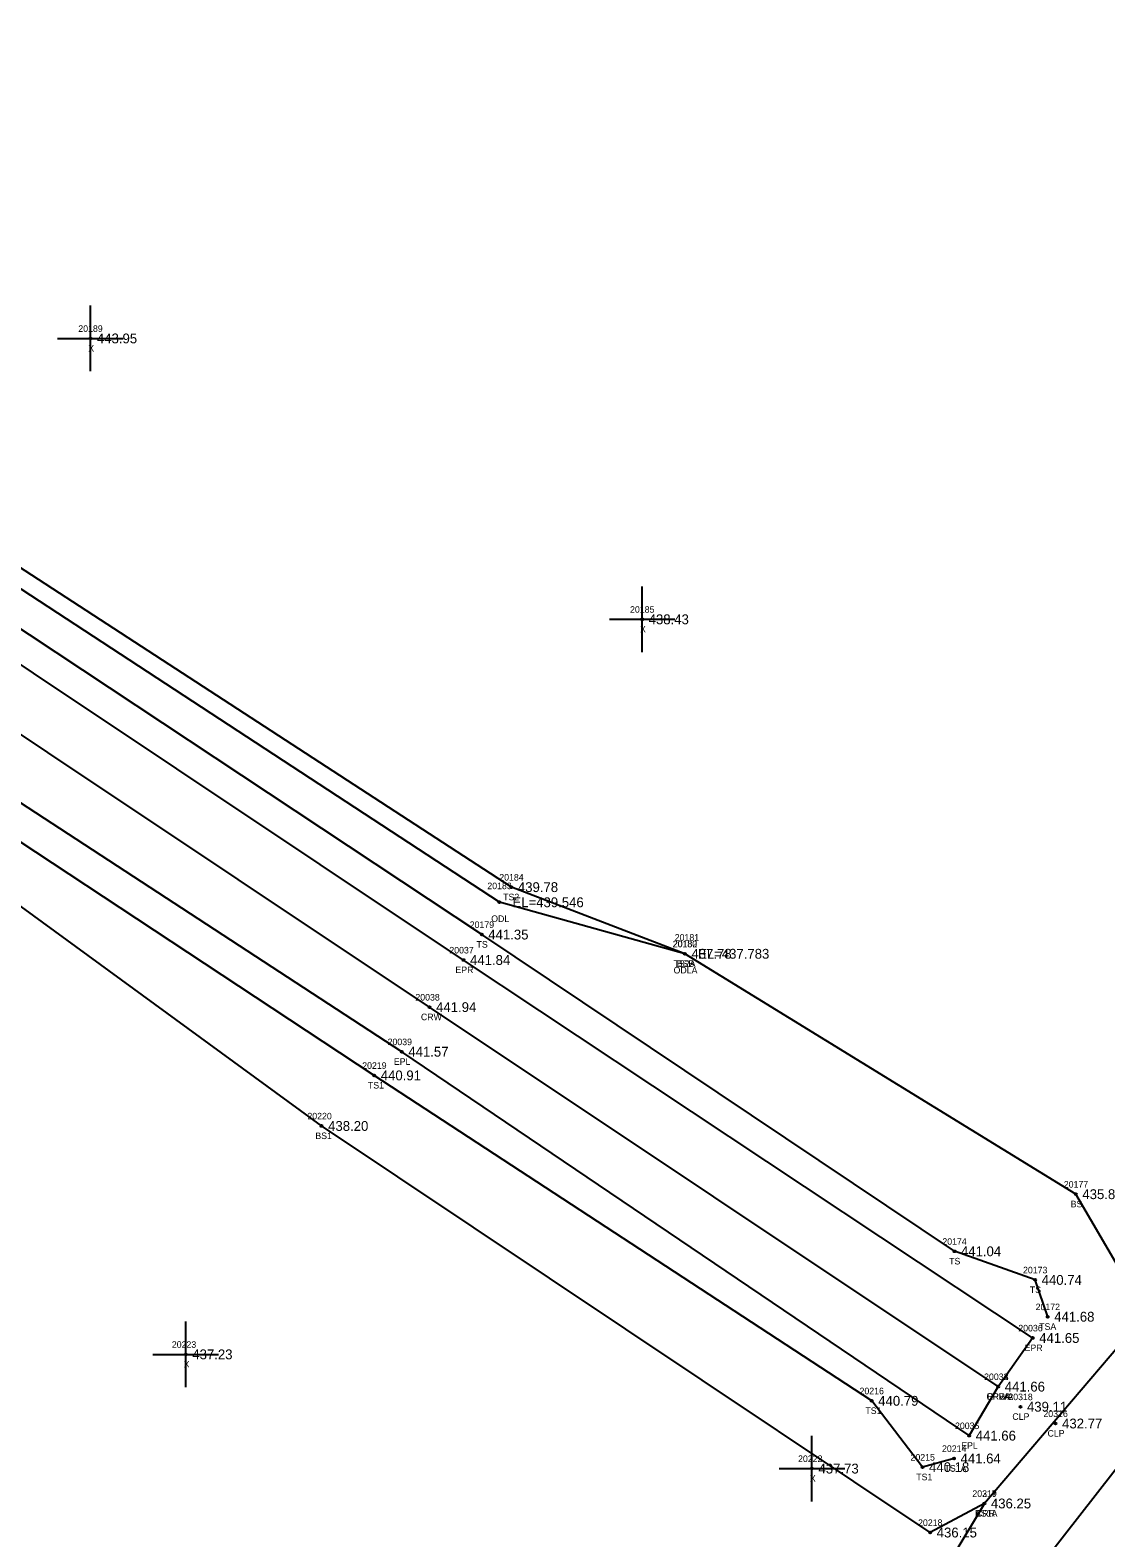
# Model space of a CAD drawing. Extents: x 1797709 to 1799052, y 896018 to 896955.
# Drawn here: x 1798214.6 to 1798378.7, y 896474.6 to 896704.4 of the extents above; entities that cross this region are included whole.
import ezdxf

# ---------------------------------------------------------------- set-up
doc = ezdxf.new("R2010")
doc.units = 0
for name, color, linetype in [('RD_DTM_BkLn1', 7, 'Continuous'), ('RD_DTM_BkLn2', 7, 'Continuous'), ('RD_DTM_BkLn_txCode', 7, 'Continuous'), ('RD_EX_H2O', 7, 'Continuous'), ('RD_EX_H2O_txCode', 7, 'Continuous'), ('RD_EX_Misc', 7, 'Continuous'), ('RD_EX_Misc_txCode', 7, 'Continuous'), ('RD_EX_Road', 7, 'Continuous'), ('RD_EX_Road_txCode', 7, 'Continuous'), ('RD_EX_TX_H2O_ELEV', 7, 'Continuous'), ('RD_EX_TX_Misc_ELEV', 7, 'Continuous'), ('RD_EX_TX_Road_ELEV', 7, 'Continuous'), ('RD_HC_Survey_ELEV', 7, 'Continuous'), ('RD_HC_Survey_txCode', 7, 'Continuous'), ('RD_SMD_Locator', 7, 'Continuous')]:
    doc.layers.add(name, color=color, linetype=linetype)

msp = doc.modelspace()

# ---------------------------------------------------------------- linework, layer by layer
at = {"layer": 'RD_DTM_BkLn1'}
msp.add_lwpolyline([(1798362.28, 896497.65), (1798275.53, 896555.51), (1798188.06, 896613.78), (1798100.6, 896671.09), (1798012.14, 896729.83), (1797925.7, 896787.19), (1797839.16, 896844.44), (1797754.21, 896899.34)], dxfattribs=at)
at = {"layer": 'RD_DTM_BkLn2'}
for points in [[(1798369.83, 896508.31), (1798367.91, 896513.92), (1798355.6, 896518.28), (1798283.49, 896566.57), (1798194.13, 896625.72), (1798108.66, 896683.13), (1798020.94, 896741.77), (1797934.88, 896798.69), (1797845.83, 896857.42), (1797757.7, 896918.3)], [(1798314.49, 896563.64), (1798288.01, 896573.8), (1798198.07, 896632.21), (1798113.28, 896689.71), (1798026.02, 896748.38), (1797939.51, 896805.48), (1797849.3, 896863.45), (1797757.7, 896918.3)], [(1798355.54, 896486.7), (1798350.74, 896485.38), (1798342.98, 896495.49), (1798267.09, 896545.1), (1798179.21, 896602.99), (1798092.54, 896661.13), (1798003.24, 896719.48), (1797918.21, 896775.43), (1797832.05, 896831.86), (1797744.82, 896887.66)], [(1798360.17, 896479.84), (1798351.9, 896475.41), (1798259.06, 896537.39), (1798197.99, 896581.94)], [(1798380.86, 896504.02), (1798383.64, 896510.73), (1798374.12, 896526.99), (1798314.49, 896563.64)]]:
    msp.add_lwpolyline(points, dxfattribs=at)
at = {"layer": 'RD_EX_H2O'}
for points in [[(1798314.49, 896563.64), (1798286.18, 896571.49), (1798196.7, 896629.98), (1798111.06, 896686.41), (1798023.38, 896745.41), (1797937.01, 896802.03), (1797847.56, 896860.46), (1797757.7, 896918.3)], [(1798652.43, 896917.58), (1798601.94, 896827.15), (1798558.78, 896718.92), (1798516.66, 896628.32), (1798463.08, 896540.21), (1798439.21, 896521.86), (1798389.85, 896497.35), (1798369.72, 896471.55), (1798343.52, 896433.35), (1798291.39, 896374.31), (1798235.39, 896326.89), (1798184.99, 896269.63), (1798095.18, 896198.01), (1798023.89, 896139.85)], [(1798502.61, 896635.66), (1798452.16, 896551.79), (1798380.86, 896504.02), (1798360.17, 896479.84), (1798335.44, 896438.68), (1798277.37, 896387.2), (1798228.36, 896339.61), (1798175.66, 896278.7), (1798083.83, 896204.11), (1798020.11, 896146.19)]]:
    msp.add_lwpolyline(points, dxfattribs=at)
at = {"layer": 'RD_EX_Misc'}
for p, q in [((1798223.79, 896652.45), (1798223.79, 896662.45)), ((1798218.79, 896657.45), (1798228.79, 896657.45)), ((1798307.96, 896609.63), (1798307.96, 896619.63)), ((1798302.96, 896614.63), (1798312.96, 896614.63)), ((1798238.34, 896497.57), (1798238.34, 896507.57)), ((1798233.34, 896502.57), (1798243.34, 896502.57)), ((1798333.87, 896480.16), (1798333.87, 896490.16)), ((1798328.87, 896485.16), (1798338.87, 896485.16))]:
    msp.add_line(p, q, dxfattribs=at)
at = {"layer": 'RD_EX_Road'}
for points in [[(1798362.28, 896497.65), (1798367.54, 896505.07), (1798280.71, 896562.69), (1798193.2, 896621.02), (1798104.98, 896679.23), (1798017.88, 896737.39), (1797930.72, 896795.63), (1797844.07, 896853.07), (1797758.11, 896906.97)], [(1798362.28, 896497.65), (1798357.85, 896490.18), (1798271.29, 896548.71), (1798183.2, 896606.17), (1798096.06, 896663.44), (1798006.57, 896721.75), (1797920.8, 896779.27), (1797834.41, 896836.87), (1797748.77, 896891.01)]]:
    msp.add_lwpolyline(points, dxfattribs=at)
at = {"layer": 'RD_SMD_Locator'}
for centre in [(1798223.79, 896657.45), (1798307.96, 896614.63), (1798288.01, 896573.8), (1798286.18, 896571.49), (1798283.49, 896566.57), (1798314.49, 896563.64), (1798314.49, 896563.64), (1798314.49, 896563.64), (1798280.71, 896562.69), (1798275.53, 896555.51), (1798271.29, 896548.71), (1798267.09, 896545.1), (1798259.06, 896537.39), (1798374.12, 896526.99), (1798355.6, 896518.28), (1798367.91, 896513.92), (1798369.83, 896508.31), (1798367.54, 896505.07), (1798238.34, 896502.57), (1798362.28, 896497.65), (1798362.28, 896497.65), (1798362.28, 896497.65), (1798342.98, 896495.49), (1798365.67, 896494.59), (1798357.85, 896490.18), (1798371.03, 896492.03), (1798350.74, 896485.38), (1798355.54, 896486.7), (1798333.87, 896485.16), (1798360.17, 896479.84), (1798360.17, 896479.84), (1798351.9, 896475.41)]:
    msp.add_circle(centre, 0.15, dxfattribs=at)

# ---------------------------------------------------------------- texts
at = {"layer": 'RD_DTM_BkLn_txCode'}
for s, p in [('20184', (1798286.17, 896574.8)), ('TS2', (1798286.76, 896571.8)), ('20179', (1798281.66, 896567.57)), ('TS', (1798282.7, 896564.57)), ('20180', (1798312.62, 896564.64)), ('20182', (1798312.66, 896564.64)), ('TS2A', (1798312.76, 896561.64)), ('BSB', (1798313.24, 896561.64)), ('20219', (1798265.26, 896546.1)), ('TS1', (1798266.13, 896543.1)), ('20220', (1798256.9, 896538.39)), ('BS1', (1798258.11, 896535.39)), ('20177', (1798372.29, 896527.99)), ('BS', (1798373.34, 896524.99)), ('20174', (1798353.76, 896519.28)), ('TS', (1798354.8, 896516.28)), ('20173', (1798366.07, 896514.92)), ('TS', (1798367.11, 896511.92)), ('20172', (1798367.99, 896509.31)), ('TSA', (1798368.54, 896506.31)), ('20216', (1798341.13, 896496.49)), ('TS1', (1798342.02, 896493.49)), ('20214', (1798353.71, 896487.7)), ('20215', (1798348.91, 896486.38)), ('TS1A', (1798354.09, 896484.7)), ('TS1', (1798349.78, 896483.38)), ('20217', (1798358.34, 896480.84)), ('BS1A', (1798358.74, 896477.84)), ('20218', (1798350.06, 896476.41))]:
    msp.add_text(s, height=1, dxfattribs=at).set_placement(p)
at = {"layer": 'RD_EX_H2O_txCode'}
for s, p in [('20183', (1798284.35, 896573.49)), ('ODL', (1798284.94, 896568.49)), ('20181', (1798312.94, 896565.64)), ('ODLA', (1798312.76, 896560.64)), ('20319', (1798358.34, 896480.84)), ('CRR', (1798358.92, 896477.84))]:
    msp.add_text(s, height=1, dxfattribs=at).set_placement(p)
at = {"layer": 'RD_EX_Misc_txCode'}
for s, p in [('20189', (1798221.95, 896658.45)), ('X', (1798223.47, 896655.45)), ('20185', (1798306.12, 896615.63)), ('X', (1798307.64, 896612.63)), ('20223', (1798236.22, 896503.57)), ('X', (1798238.02, 896500.57)), ('20222', (1798331.75, 896486.16)), ('X', (1798333.55, 896483.16))]:
    msp.add_text(s, height=1, dxfattribs=at).set_placement(p)
at = {"layer": 'RD_EX_Road_txCode'}
for s, p in [('20037', (1798278.55, 896563.69)), ('EPR', (1798279.48, 896560.69)), ('20039', (1798269.13, 896549.71)), ('EPL', (1798270.08, 896546.71)), ('20036', (1798365.35, 896506.07)), ('EPR', (1798366.31, 896503.07)), ('20032', (1798360.13, 896498.65)), ('20033', (1798360.13, 896498.65)), ('EPRA', (1798360.57, 896495.65)), ('EPLA', (1798360.59, 896495.65)), ('20035', (1798355.69, 896491.18)), ('EPL', (1798356.64, 896488.18))]:
    msp.add_text(s, height=1, dxfattribs=at).set_placement(p)
at = {"layer": 'RD_EX_TX_H2O_ELEV'}
for s, p in [('EL=439.546', (1798288.18, 896570.74)), ('EL=437.783', (1798316.49, 896562.89)), ('436.25', (1798361.17, 896479.09))]:
    msp.add_text(s, height=1.5, dxfattribs=at).set_placement(p)
at = {"layer": 'RD_EX_TX_Misc_ELEV'}
for s, p in [('443.95', (1798224.79, 896656.7)), ('438.43', (1798308.96, 896613.88)), ('439.78', (1798289.01, 896573.05)), ('441.35', (1798284.49, 896565.82)), ('437.78', (1798315.49, 896562.89)), ('437.78', (1798315.49, 896562.89)), ('440.91', (1798268.09, 896544.35)), ('438.20', (1798260.06, 896536.64)), ('435.85', (1798375.12, 896526.24)), ('441.04', (1798356.6, 896517.53)), ('440.74', (1798368.91, 896513.17)), ('441.68', (1798370.83, 896507.56)), ('437.23', (1798239.34, 896501.82)), ('440.79', (1798343.98, 896494.74)), ('437.73', (1798334.87, 896484.41)), ('440.18', (1798351.74, 896484.63)), ('441.64', (1798356.54, 896485.95)), ('436.25', (1798361.17, 896479.09)), ('436.15', (1798352.9, 896474.66))]:
    msp.add_text(s, height=1.5, dxfattribs=at).set_placement(p)
at = {"layer": 'RD_EX_TX_Road_ELEV'}
for s, p in [('441.84', (1798281.71, 896561.94)), ('441.57', (1798272.29, 896547.96)), ('441.65', (1798368.54, 896504.32)), ('441.66', (1798363.28, 896496.9)), ('441.66', (1798363.28, 896496.9)), ('441.66', (1798358.85, 896489.43))]:
    msp.add_text(s, height=1.5, dxfattribs=at).set_placement(p)
at = {"layer": 'RD_HC_Survey_ELEV'}
for s, p in [('441.94', (1798276.53, 896554.76)), ('441.66', (1798363.28, 896496.9)), ('439.11', (1798366.67, 896493.84)), ('432.77', (1798372.03, 896491.28))]:
    msp.add_text(s, height=1.5, dxfattribs=at).set_placement(p)
at = {"layer": 'RD_HC_Survey_txCode'}
for s, p in [('20038', (1798273.37, 896556.51)), ('CRW', (1798274.22, 896553.51)), ('20034', (1798360.13, 896498.65)), ('CRWA', (1798360.48, 896495.65)), ('20318', (1798363.83, 896495.59)), ('CLP', (1798364.44, 896492.59)), ('20316', (1798369.18, 896493.03)), ('CLP', (1798369.81, 896490.03))]:
    msp.add_text(s, height=1, dxfattribs=at).set_placement(p)

doc.saveas('drawing.dxf')
